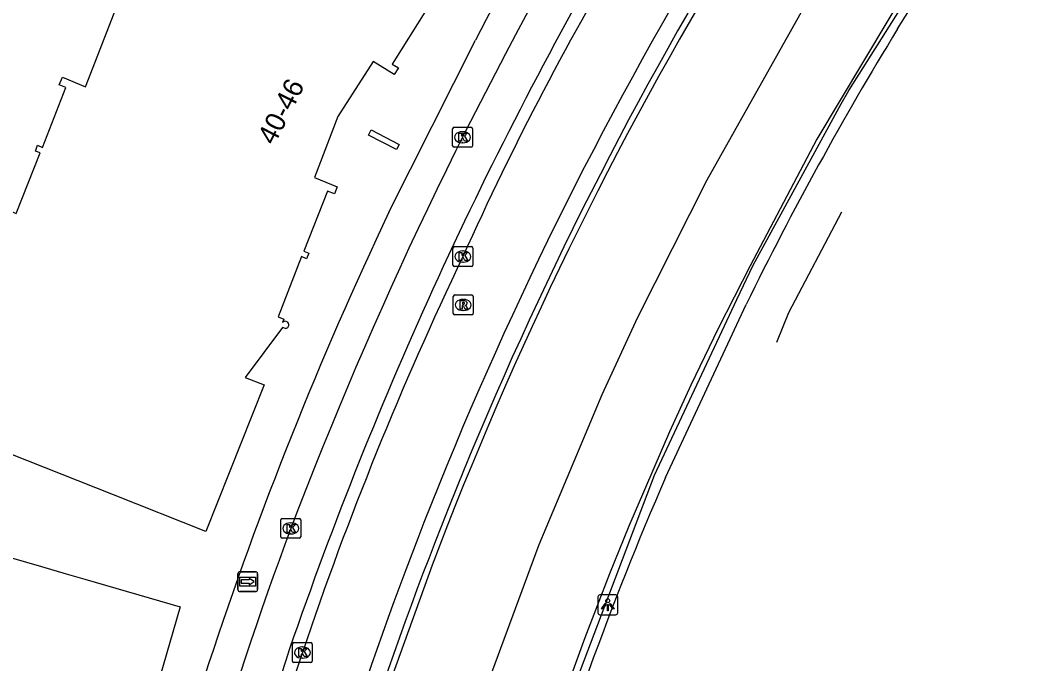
# Model space of a CAD drawing. Extents: x 158352 to 159489, y 383828 to 384597.
# Drawn here: x 159242.1 to 159292.6, y 384156.5 to 384188.9 of the extents above; entities that cross this region are included whole.
import ezdxf

# ---------------------------------------------------------------- set-up
doc = ezdxf.new("R2010")
doc.units = 0
for name, color, linetype in [('IMGEO_Fietspad_gesloten', 7, 'Continuous'), ('IMGEO_Kolk', 7, 'Continuous'), ('IMGEO_Lichtpunt', 7, 'Continuous'), ('IMGEO_Lijnafwatering', 7, 'Continuous'), ('IMGEO_Muur', 7, 'Continuous'), ('IMGEO_Pand', 7, 'Continuous'), ('IMGEO_Pand_nummerreeks', 7, 'Continuous'), ('IMGEO_Rijbaan_regionaal_gesloten', 7, 'Continuous'), ('IMGEO_Rioolput', 7, 'Continuous'), ('IMGEO_Voetpad_open', 7, 'Continuous'), ('IMGEO_Wegwijzer', 7, 'Continuous')]:
    doc.layers.add(name, color=color, linetype=linetype)

msp = doc.modelspace()

# ---------------------------------------------------------------- linework, layer by layer
at = {"layer": 'IMGEO_Fietspad_gesloten'}
for centre, radius, start, end in [((159456.743, 384086.718), 215.07, 149.83056, 159.14628), ((159450.178, 384090.144), 205.72, 149.76377, 160.97354), ((159423.293, 384100.667), 178.849, 159.50752, 168.31277), ((159446.053, 384094.642), 200.375, 161.8048, 173.89034)]:
    msp.add_arc(centre, radius, start, end, dxfattribs=at)
at = {"layer": 'IMGEO_Kolk'}
for p, q in [((159263.906, 384182.533), (159263.906, 384183.385)), ((159263.981, 384183.459), (159264.833, 384183.459)), ((159264.394, 384183.239), (159264.419, 384183.239)), ((159264.907, 384183.385), (159264.907, 384182.533)), ((159264.417, 384182.679), (159264.392, 384182.679)), ((159264.833, 384182.459), (159263.981, 384182.459)), ((159263.925, 384176.531), (159263.925, 384177.383)), ((159264, 384177.457), (159264.852, 384177.457)), ((159264.413, 384177.237), (159264.438, 384177.237)), ((159264.926, 384177.383), (159264.926, 384176.531)), ((159264.436, 384176.677), (159264.411, 384176.677)), ((159264.852, 384176.457), (159264, 384176.457)), ((159255.26, 384162.853), (159255.26, 384163.705)), ((159255.335, 384163.779), (159256.187, 384163.779)), ((159255.748, 384163.559), (159255.773, 384163.559)), ((159256.261, 384163.705), (159256.261, 384162.853)), ((159255.771, 384162.999), (159255.746, 384162.999)), ((159256.187, 384162.779), (159255.335, 384162.779)), ((159255.843, 384156.605), (159255.843, 384157.457)), ((159255.918, 384157.531), (159256.77, 384157.531)), ((159256.844, 384157.457), (159256.844, 384156.605)), ((159256.331, 384157.311), (159256.356, 384157.311)), ((159256.77, 384156.531), (159255.918, 384156.531)), ((159256.354, 384156.751), (159256.329, 384156.751))]:
    msp.add_line(p, q, dxfattribs=at)
for points in [[(159263.906, 384182.533), (159263.906, 384183.385)], [(159263.981, 384183.459), (159264.833, 384183.459)], [(159264.227, 384183.159), (159264.35, 384183.159), (159264.35, 384183.008), (159264.48, 384183.159), (159264.644, 384183.159), (159264.498, 384183.008), (159264.651, 384182.759), (159264.499, 384182.759), (159264.414, 384182.923), (159264.35, 384182.856), (159264.35, 384182.759), (159264.227, 384182.759), (159264.227, 384183.159)], [(159264.907, 384183.385), (159264.907, 384182.533)], [(159264.833, 384182.459), (159263.981, 384182.459)], [(159263.925, 384176.531), (159263.925, 384177.383)], [(159264, 384177.457), (159264.852, 384177.457)], [(159264.246, 384177.157), (159264.369, 384177.157), (159264.369, 384177.006), (159264.499, 384177.157), (159264.663, 384177.157), (159264.517, 384177.006), (159264.67, 384176.757), (159264.518, 384176.757), (159264.433, 384176.921), (159264.369, 384176.854), (159264.369, 384176.757), (159264.246, 384176.757), (159264.246, 384177.157)], [(159264.926, 384177.383), (159264.926, 384176.531)], [(159264.852, 384176.457), (159264, 384176.457)], [(159255.26, 384162.853), (159255.26, 384163.705)], [(159255.335, 384163.779), (159256.187, 384163.779)], [(159255.581, 384163.479), (159255.704, 384163.479), (159255.704, 384163.328), (159255.834, 384163.479), (159255.998, 384163.479), (159255.852, 384163.328), (159256.005, 384163.079), (159255.853, 384163.079), (159255.768, 384163.243), (159255.704, 384163.176), (159255.704, 384163.079), (159255.581, 384163.079), (159255.581, 384163.479)], [(159256.261, 384163.705), (159256.261, 384162.853)], [(159256.187, 384162.779), (159255.335, 384162.779)], [(159255.843, 384156.605), (159255.843, 384157.457)], [(159255.918, 384157.531), (159256.77, 384157.531)], [(159256.844, 384157.457), (159256.844, 384156.605)], [(159256.164, 384157.231), (159256.287, 384157.231), (159256.287, 384157.08), (159256.417, 384157.231), (159256.581, 384157.231), (159256.435, 384157.08), (159256.588, 384156.831), (159256.436, 384156.831), (159256.351, 384156.995), (159256.287, 384156.928), (159256.287, 384156.831), (159256.164, 384156.831), (159256.164, 384157.231)], [(159256.77, 384156.531), (159255.918, 384156.531)]]:
    msp.add_lwpolyline(points, dxfattribs=at)
for centre, start, end in [((159263.983, 384183.383), 91.552, 178.448), ((159263.983, 384183.383), 91.552, 178.448), ((159264.831, 384183.383), 1.552, 88.448), ((159264.831, 384183.383), 1.552, 88.448), ((159263.983, 384182.535), 181.552, 268.448), ((159263.983, 384182.535), 181.552, 268.448), ((159264.831, 384182.535), 271.552, 358.448), ((159264.831, 384182.535), 271.552, 358.448), ((159264.002, 384177.381), 91.552, 178.448), ((159264.002, 384177.381), 91.552, 178.448), ((159264.85, 384177.381), 1.552, 88.448), ((159264.85, 384177.381), 1.552, 88.448), ((159264.002, 384176.533), 181.552, 268.448), ((159264.002, 384176.533), 181.552, 268.448), ((159264.85, 384176.533), 271.552, 358.448), ((159264.85, 384176.533), 271.552, 358.448), ((159255.337, 384163.703), 91.552, 178.448), ((159255.337, 384163.703), 91.552, 178.448), ((159256.185, 384163.703), 1.552, 88.448), ((159256.185, 384163.703), 1.552, 88.448), ((159255.337, 384162.855), 181.552, 268.448), ((159255.337, 384162.855), 181.552, 268.448), ((159256.185, 384162.855), 271.552, 358.448), ((159256.185, 384162.855), 271.552, 358.448), ((159255.92, 384157.455), 91.552, 178.448), ((159255.92, 384157.455), 91.552, 178.448), ((159256.768, 384157.455), 1.552, 88.448), ((159256.768, 384157.455), 1.552, 88.448), ((159255.92, 384156.607), 181.552, 268.448), ((159255.92, 384156.607), 181.552, 268.448), ((159256.768, 384156.607), 271.552, 358.448), ((159256.768, 384156.607), 271.552, 358.448)]:
    msp.add_arc(centre, 0.0765, start, end, dxfattribs=at)
for centre, major_axis, ratio, start_param, end_param in [((159264.393, 384182.959), (-0.387, 0.002), 0.722429, 4.712389, 7.853982), ((159264.418, 384182.959), (-0.39, 0.002), 0.717154, 1.570796, 4.712389), ((159264.412, 384176.957), (-0.387, 0.002), 0.722429, 4.712389, 7.853982), ((159264.437, 384176.957), (-0.39, 0.002), 0.717154, 1.570796, 4.712389), ((159255.747, 384163.279), (-0.387, 0.002), 0.722429, 4.712389, 7.853982), ((159255.772, 384163.279), (-0.39, 0.002), 0.717154, 1.570796, 4.712389), ((159256.33, 384157.031), (-0.387, 0.002), 0.722429, 4.712389, 7.853982), ((159256.355, 384157.031), (-0.39, 0.002), 0.717154, 1.570796, 4.712389)]:
    msp.add_ellipse(centre, major_axis=major_axis, ratio=ratio, start_param=start_param, end_param=end_param, dxfattribs=at)
at = {"layer": 'IMGEO_Lichtpunt'}
for p, q in [((159272.124, 384159.931), (159271.316, 384159.931)), ((159272.124, 384159.931), (159271.316, 384159.931)), ((159271.222, 384159.836), (159271.222, 384159.029)), ((159271.222, 384159.836), (159271.222, 384159.029)), ((159272.218, 384159.029), (159272.218, 384159.836)), ((159272.218, 384159.029), (159272.218, 384159.836)), ((159271.316, 384158.935), (159272.124, 384158.935)), ((159271.316, 384158.935), (159272.124, 384158.935))]:
    msp.add_line(p, q, dxfattribs=at)
for points in [[(159271.596, 384159.5), (159271.635, 384159.472), (159271.447, 384159.21), (159271.409, 384159.237), (159271.596, 384159.5)], [(159271.698, 384159.452), (159271.745, 384159.452), (159271.745, 384159.13), (159271.698, 384159.13), (159271.698, 384159.452)], [(159271.808, 384159.472), (159271.846, 384159.499), (159272.033, 384159.237), (159271.994, 384159.209), (159271.808, 384159.472)]]:
    msp.add_lwpolyline(points, dxfattribs=at)
msp.add_circle((159271.721, 384159.634), 0.0994, dxfattribs=at)
for centre, start, end in [((159271.316, 384159.836), 90, 180), ((159271.316, 384159.836), 90, 180), ((159272.124, 384159.836), 0, 90), ((159272.124, 384159.836), 0, 90), ((159271.316, 384159.029), 180, 270), ((159271.316, 384159.029), 180, 270), ((159272.124, 384159.029), 270, 0), ((159272.124, 384159.029), 270, 360)]:
    msp.add_arc(centre, 0.0946, start, end, dxfattribs=at)
at = {"layer": 'IMGEO_Lijnafwatering'}
for points in [[(159286.997, 384190.817), (159282.252, 384182.871), (159278.88, 384176.495), (159277.28, 384173.336)], [(159277.28, 384173.336), (159275.906, 384170.483), (159274.824, 384168.133), (159272.772, 384163.384), (159271.802, 384160.986), (159270.567, 384157.765), (159269.959, 384156.109), (159269.535, 384154.897)]]:
    msp.add_lwpolyline(points, dxfattribs=at)
at = {"layer": 'IMGEO_Muur'}
msp.add_lwpolyline([(159262.877, 384161.42), (159260.47, 384154.737)], dxfattribs=at)
for centre, radius, start, end in [((159438.68, 384094.885), 187.972, 148.6861, 159.27012), ((159444.494, 384092.188), 194.647, 148.90039, 158.53981), ((159422.322, 384100.525), 170.962, 158.4217, 167.60222)]:
    msp.add_arc(centre, radius, start, end, dxfattribs=at)
at = {"layer": 'IMGEO_Pand'}
for points in [[(159240.112, 384176.165), (159241.049, 384175.794), (159241.371, 384178.932), (159241.26, 384179.019), (159241.285, 384179.211), (159241.473, 384179.254), (159241.579, 384179.08), (159241.641, 384179.255), (159241.94, 384179.13), (159243.147, 384182.172), (159242.903, 384182.261), (159243.009, 384182.555), (159243.254, 384182.451), (159244.439, 384185.462), (159244.105, 384185.596), (159244.261, 384185.986), (159245.418, 384185.502), (159246.992, 384189.503)], [(159262.601, 384189.389), (159260.86, 384186.643), (159261.176, 384186.45), (159260.971, 384186.113), (159259.915, 384186.773), (159258.127, 384184.002), (159256.954, 384180.934), (159258.101, 384180.469), (159257.964, 384180.112), (159257.61, 384180.248), (159256.424, 384177.235), (159256.677, 384177.129), (159256.555, 384176.846), (159256.298, 384176.957), (159255.124, 384173.922), (159255.405, 384173.806), (159255.337, 384173.633)], [(159259.806, 384183.335), (159261.223, 384182.601), (159261.086, 384182.336), (159259.668, 384183.069), (159259.806, 384183.335)], [(159255.502, 384173.343), (159255.351, 384173.394), (159253.466, 384170.875), (159254.416, 384170.496), (159251.485, 384163.13), (159246.836, 384164.97), (159237.198, 384168.781), (159240.112, 384176.165)], [(159255.584, 384173.667), (159255.652, 384173.569)], [(159227.01, 384114.546), (159229.977, 384135.614), (159230.051, 384136.143), (159231.424, 384135.814), (159231.492, 384137.793), (159231.969, 384139.959), (159232.699, 384141.748), (159231.84, 384142.039), (159231.808, 384141.929), (159231.32, 384142.053), (159231.444, 384142.482), (159237.395, 384163.043), (159243.218, 384161.354), (159244.455, 384160.995), (159245.386, 384160.725), (159250.188, 384159.332)], [(159250.188, 384159.332), (159244.538, 384139.822), (159244.004, 384139.953), (159244.045, 384140.269), (159242.416, 384139.313), (159242.857, 384137.643), (159242.392, 384135.444), (159241.299, 384134.114), (159242.428, 384132.585), (159242.489, 384132.849), (159243, 384132.767), (159240.163, 384112.68)]]:
    msp.add_lwpolyline(points, dxfattribs=at)
for radius, start, end in [(0.179, 53.7966, 141.8787), (0.181, 277.7868, 15.0674)]:
    msp.add_arc((159255.478, 384173.522), radius, start, end, dxfattribs=at)
at = {"layer": 'IMGEO_Rijbaan_regionaal_gesloten'}
for points in [[(159286.308, 384188.412), (159289.839, 384194.026), (159292.62, 384197.927)], [(159260.803, 384111.778), (159262.475, 384126.232), (159264.678, 384137.417), (159268.735, 384151.895), (159274.068, 384165.954), (159278.21, 384174.788), (159279.041, 384176.526), (159283.476, 384184.645), (159283.856, 384185.315), (159290.842, 384196.371)], [(159281.68, 384189.635), (159276.714, 384180.808), (159273.22, 384173.893), (159271.418, 384169.994), (159268.255, 384162.454), (159265.459, 384154.913), (159263.105, 384147.3), (159260.972, 384139.575), (159259.133, 384130.895), (159257.956, 384123.759), (159257.036, 384115.814), (159256.668, 384111.768), (159256.448, 384107.759), (159256.374, 384103.824), (159256.337, 384099.851), (159257.073, 384078.885), (159257.992, 384055.492), (159258.838, 384034.563), (159261.56, 384009.074), (159263.73, 383989.138), (159264.746, 383979.804)], [(159283.483, 384179.194), (159280.817, 384174.126), (159280.211, 384172.631)], [(159274.632, 384165.847), (159278.679, 384174.544)]]:
    msp.add_lwpolyline(points, dxfattribs=at)
for centre, radius, start, end in [((159401.778, 384115.337), 150.541, 148.78074, 155.83783), ((159441.97, 384093.226), 192.797, 148.78432, 158.60127), ((159434.165, 384098.041), 173.288, 148.56656, 153.8017), ((159424.366, 384100.491), 177.278, 154.44809, 168.3553), ((159426.633, 384099.786), 165.736, 156.50994, 170.96437), ((159419.551, 384101.572), 168.878, 158.46247, 167.70632)]:
    msp.add_arc(centre, radius, start, end, dxfattribs=at)
at = {"layer": 'IMGEO_Rioolput'}
for p, q in [((159263.939, 384174.098), (159263.939, 384174.95)), ((159264.014, 384175.024), (159264.866, 384175.024)), ((159264.427, 384174.804), (159264.452, 384174.804)), ((159264.94, 384174.95), (159264.94, 384174.098)), ((159264.45, 384174.244), (159264.425, 384174.244)), ((159264.866, 384174.024), (159264.014, 384174.024))]:
    msp.add_line(p, q, dxfattribs=at)
for points in [[(159263.939, 384174.098), (159263.939, 384174.95)], [(159264.014, 384175.024), (159264.866, 384175.024)], [(159264.528, 384174.722), (159264.276, 384174.724), (159264.276, 384174.324)], [(159264.454, 384174.643), (159264.4, 384174.643), (159264.4, 384174.562)], [(159264.94, 384174.95), (159264.94, 384174.098)], [(159264.276, 384174.324), (159264.4, 384174.324), (159264.4, 384174.486), (159264.411, 384174.486)], [(159264.4, 384174.562), (159264.452, 384174.562)], [(159264.458, 384174.457), (159264.529, 384174.324), (159264.669, 384174.324), (159264.604, 384174.45)], [(159264.866, 384174.024), (159264.014, 384174.024)]]:
    msp.add_lwpolyline(points, dxfattribs=at)
for centre, radius, start, end in [((159264.016, 384174.948), 0.0765, 91.552, 178.448), ((159264.016, 384174.948), 0.0765, 91.552, 178.448), ((159264.46, 384174.547), 0.0964, 77.0061, 93.1865), ((159264.474, 384174.604), 0.0378, 276.6634, 79.6772), ((159264.527, 384174.612), 0.109, 350.3612, 89.416), ((159264.525, 384174.612), 0.112, 277.5842, 350.9817), ((159264.864, 384174.948), 0.0765, 1.552, 88.448), ((159264.864, 384174.948), 0.0765, 1.552, 88.448), ((159264.016, 384174.1), 0.0765, 181.552, 268.448), ((159264.016, 384174.1), 0.0765, 181.552, 268.448), ((159264.41, 384174.433), 0.0533, 26.0293, 88.6989), ((159264.436, 384174.751), 0.19, 274.7715, 282.9687), ((159264.509, 384174.397), 0.108, 29.5134, 73.7905), ((159264.864, 384174.1), 0.0765, 271.552, 358.448), ((159264.864, 384174.1), 0.0765, 271.552, 358.448)]:
    msp.add_arc(centre, radius, start, end, dxfattribs=at)
for centre, major_axis, ratio, start_param, end_param in [((159264.426, 384174.524), (-0.387, 0.002), 0.722429, 4.712389, 7.853982), ((159264.451, 384174.524), (-0.39, 0.002), 0.717154, 1.570796, 4.712389)]:
    msp.add_ellipse(centre, major_axis=major_axis, ratio=ratio, start_param=start_param, end_param=end_param, dxfattribs=at)
at = {"layer": 'IMGEO_Voetpad_open'}
msp.add_lwpolyline([(159260.704, 384179.195), (159265.058, 384187.841)], dxfattribs=at)
for centre, radius, start, end in [((159382.55, 384127.726), 131.978, 144.79534, 152.90329), ((159438.295, 384095.068), 196.509, 154.65252, 161.79594), ((159429.57, 384099.226), 186.926, 162.17101, 171.42777)]:
    msp.add_arc(centre, radius, start, end, dxfattribs=at)
at = {"layer": 'IMGEO_Wegwijzer'}
for p, q in [((159253.096, 384160.198), (159253.096, 384160.998)), ((159253.096, 384160.998), (159253.096, 384160.198)), ((159253.196, 384161.098), (159253.986, 384161.098)), ((159253.986, 384161.098), (159253.196, 384161.098)), ((159254.086, 384160.998), (159254.086, 384160.198)), ((159254.086, 384160.198), (159254.086, 384160.998)), ((159253.986, 384160.098), (159253.196, 384160.098)), ((159253.196, 384160.098), (159253.986, 384160.098))]:
    msp.add_line(p, q, dxfattribs=at)
for points in [[(159253.197, 384160.83), (159253.985, 384160.83), (159253.985, 384160.366), (159253.197, 384160.366), (159253.197, 384160.83)], [(159253.262, 384160.682), (159253.262, 384160.598), (159253.262, 384160.514), (159253.673, 384160.514), (159253.673, 384160.431), (159253.92, 384160.598), (159253.673, 384160.765), (159253.673, 384160.682), (159253.262, 384160.682)]]:
    msp.add_lwpolyline(points, dxfattribs=at)
for centre, start, end in [((159253.196, 384160.998), 90, 180), ((159253.196, 384160.998), 90, 180), ((159253.986, 384160.998), 0, 90), ((159253.986, 384160.998), 360, 90), ((159253.196, 384160.198), 180, 270), ((159253.196, 384160.198), 180, 270), ((159253.986, 384160.198), 270, 0), ((159253.986, 384160.198), 270, 0)]:
    msp.add_arc(centre, 0.1, start, end, dxfattribs=at)

# ---------------------------------------------------------------- texts
at = {"layer": 'IMGEO_Pand_nummerreeks'}
msp.add_text('40-46', height=1, rotation=63.1101, dxfattribs=at).set_placement((159254.93, 384182.515))

doc.saveas('drawing.dxf')
